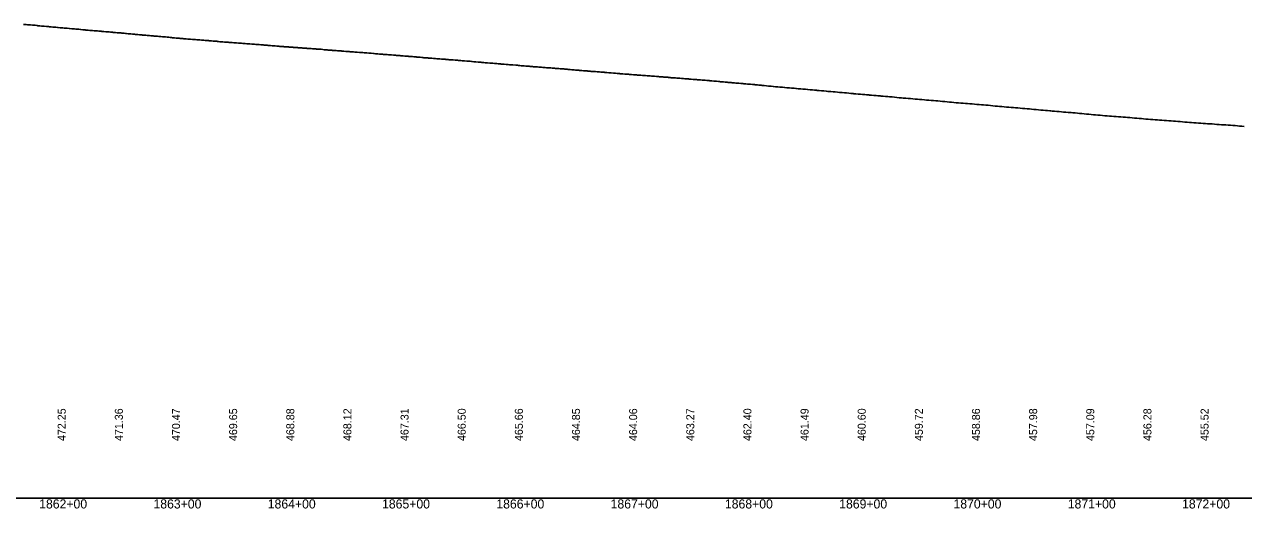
# Model space of a CAD drawing. Extents: x 2017200 to 2047700, y 854850 to 893350.
# Drawn here: x 2041163 to 2042230, y 856091 to 856515 of the extents above; entities that cross this region are included whole.
import ezdxf

# ---------------------------------------------------------------- set-up
doc = ezdxf.new("R2010")
doc.units = 0
for name, color, linetype in [('RD_DDB_Profile_EX', 7, 'Continuous'), ('RD_DDB_StaTX', 7, 'Continuous'), ('RD_DDB_StripGrade', 7, 'Continuous'), ('RD_GPK_Profile_Cell', 7, 'Continuous')]:
    doc.layers.add(name, color=color, linetype=linetype)

msp = doc.modelspace()

# ---------------------------------------------------------------- linework, layer by layer
at = {"layer": 'RD_DDB_Profile_EX'}
msp.add_lwpolyline([(2041162.2, 856514.6), (2041163.9, 856514.5), (2041164.3, 856514.5), (2041165.5, 856514.3), (2041166.3, 856514.3), (2041167.8, 856514.2), (2041168.2, 856514.1), (2041169.9, 856514), (2041170.2, 856513.9), (2041172.2, 856513.8), (2041174, 856513.6), (2041174.5, 856513.5), (2041175.6, 856513.4), (2041176.3, 856513.4), (2041177.8, 856513.2), (2041178.3, 856513.2), (2041179.9, 856513.1), (2041180.2, 856513), (2041182.2, 856512.8), (2041184.2, 856512.7), (2041184.6, 856512.6), (2041185.6, 856512.5), (2041186.4, 856512.5), (2041187.8, 856512.3), (2041188.3, 856512.3), (2041189.9, 856512.1), (2041190.3, 856512.1), (2041191.9, 856511.9), (2041192.3, 856511.9), (2041194.2, 856511.7), (2041194.8, 856511.7), (2041195.6, 856511.6), (2041196.5, 856511.5), (2041197.8, 856511.4), (2041198.4, 856511.4), (2041199.9, 856511.2), (2041200.3, 856511.2), (2041202, 856511.1), (2041202.3, 856511), (2041204.3, 856510.8), (2041206, 856510.7), (2041206.6, 856510.6), (2041207.9, 856510.5), (2041208.5, 856510.5), (2041209.9, 856510.4), (2041210.4, 856510.3), (2041212, 856510.1), (2041212.3, 856510.1), (2041214, 856510), (2041214.3, 856509.9), (2041216, 856509.8), (2041216.7, 856509.7), (2041217.9, 856509.6), (2041218.6, 856509.6), (2041220, 856509.4), (2041220.5, 856509.4), (2041222, 856509.3), (2041222.4, 856509.2), (2041224, 856509.1), (2041224.3, 856509), (2041226, 856508.9), (2041226.9, 856508.9), (2041228, 856508.7), (2041228.6, 856508.7), (2041230, 856508.6), (2041230.5, 856508.5), (2041232, 856508.4), (2041232.4, 856508.3), (2041234.1, 856508.2), (2041234.4, 856508.2), (2041236.1, 856508), (2041237.1, 856508), (2041238.1, 856507.9), (2041238.8, 856507.8), (2041240.1, 856507.7), (2041240.6, 856507.6), (2041242.1, 856507.5), (2041242.5, 856507.4), (2041244.1, 856507.3), (2041244.5, 856507.3), (2041246.1, 856507.1), (2041247.3, 856507.1), (2041248.2, 856507), (2041249, 856506.9), (2041250.2, 856506.8), (2041251.4, 856506.7), (2041252.1, 856506.6), (2041253.6, 856506.5), (2041254.1, 856506.4), (2041255.7, 856506.3), (2041256.1, 856506.3), (2041257.5, 856506.2), (2041258.3, 856506.1), (2041259.1, 856506), (2041260.2, 856505.9), (2041261.4, 856505.8), (2041262.2, 856505.7), (2041263.6, 856505.6), (2041264.2, 856505.5), (2041265.7, 856505.4), (2041266.2, 856505.3), (2041267.8, 856505.2), (2041268.4, 856505.2), (2041269.1, 856505.1), (2041270.3, 856505), (2041271.5, 856504.9), (2041272.3, 856504.8), (2041273.6, 856504.7), (2041274.2, 856504.6), (2041275.7, 856504.5), (2041276.2, 856504.4), (2041277.8, 856504.3), (2041278.6, 856504.2), (2041279.2, 856504.2), (2041280.4, 856504.1), (2041281.5, 856504), (2041282.3, 856503.9), (2041283.7, 856503.8), (2041284.3, 856503.7), (2041285.8, 856503.6), (2041286.3, 856503.6), (2041287.8, 856503.4), (2041288.8, 856503.3), (2041289.2, 856503.3), (2041290.5, 856503.2), (2041291.6, 856503.1), (2041292.4, 856503), (2041293.7, 856502.9), (2041294.3, 856502.8), (2041295.8, 856502.7), (2041296.3, 856502.7), (2041297.9, 856502.5), (2041298.3, 856502.5), (2041299.3, 856502.4), (2041300.7, 856502.3), (2041301.6, 856502.2), (2041302.5, 856502.1), (2041303.8, 856502), (2041304.4, 856501.9), (2041305.9, 856501.8), (2041306.4, 856501.8), (2041307.9, 856501.7), (2041308.3, 856501.7), (2041309.9, 856501.5), (2041310.8, 856501.5), (2041311.7, 856501.4), (2041312.6, 856501.3), (2041313.8, 856501.2), (2041314.5, 856501.1), (2041315.9, 856501), (2041316.4, 856501), (2041317.9, 856500.9), (2041318.4, 856500.8), (2041320, 856500.7), (2041321, 856500.6), (2041321.8, 856500.6), (2041322.7, 856500.5), (2041323.9, 856500.4), (2041324.5, 856500.3), (2041326, 856500.1), (2041326.5, 856500.1), (2041328, 856500), (2041328.4, 856500), (2041330, 856499.9), (2041331.1, 856499.8), (2041331.9, 856499.7), (2041332.8, 856499.6), (2041334, 856499.5), (2041334.6, 856499.4), (2041336, 856499.3), (2041336.5, 856499.3), (2041338, 856499.2), (2041338.4, 856499.2), (2041340, 856499.1), (2041341.3, 856499), (2041342, 856498.9), (2041342.9, 856498.8), (2041344.1, 856498.8), (2041344.7, 856498.7), (2041346.1, 856498.6), (2041346.6, 856498.5), (2041348.1, 856498.4), (2041348.5, 856498.4), (2041350.1, 856498.2), (2041351.6, 856498.2), (2041352.1, 856498.1), (2041352.7, 856498.1), (2041354.1, 856498), (2041355.3, 856497.9), (2041356.1, 856497.8), (2041357.5, 856497.7), (2041358.1, 856497.6), (2041359.6, 856497.5), (2041360.1, 856497.5), (2041361.9, 856497.4), (2041362.3, 856497.3), (2041362.7, 856497.3), (2041364.2, 856497.2), (2041365.3, 856497.1), (2041366.2, 856497), (2041367.5, 856496.9), (2041368.2, 856496.9), (2041369.6, 856496.8), (2041370.2, 856496.7), (2041371.7, 856496.6), (2041372.8, 856496.5), (2041374.3, 856496.4), (2041375.3, 856496.3), (2041376.3, 856496.2), (2041377.6, 856496.1), (2041378.2, 856496.1), (2041379.7, 856495.9), (2041380.2, 856495.9), (2041381.8, 856495.8), (2041382.2, 856495.8), (2041383.8, 856495.6), (2041384.4, 856495.6), (2041385.4, 856495.5), (2041386.3, 856495.4), (2041387.6, 856495.4), (2041388.3, 856495.3), (2041389.7, 856495.2), (2041390.3, 856495.1), (2041391.8, 856495), (2041392.2, 856495), (2041393.9, 856494.9), (2041394.6, 856494.8), (2041395.5, 856494.8), (2041396.4, 856494.7), (2041397.7, 856494.6), (2041398.4, 856494.5), (2041399.8, 856494.4), (2041400.3, 856494.4), (2041401.8, 856494.3), (2041402.3, 856494.2), (2041403.9, 856494.1), (2041404.7, 856494), (2041405.5, 856494), (2041406.5, 856493.9), (2041407.7, 856493.8), (2041408.4, 856493.8), (2041409.8, 856493.7), (2041410.4, 856493.6), (2041411.9, 856493.5), (2041412.3, 856493.5), (2041413.9, 856493.4), (2041414.9, 856493.3), (2041415.6, 856493.2), (2041416.6, 856493.2), (2041417.8, 856493.1), (2041418.5, 856493), (2041419.9, 856492.9), (2041420.4, 856492.9), (2041421.9, 856492.8), (2041422.4, 856492.8), (2041423.9, 856492.6), (2041425.1, 856492.5), (2041425.7, 856492.5), (2041426.8, 856492.4), (2041427.8, 856492.3), (2041428.6, 856492.2), (2041429.9, 856492.1), (2041430.5, 856492.1), (2041432, 856492), (2041432.4, 856491.9), (2041434, 856491.8), (2041435.4, 856491.7), (2041435.8, 856491.7), (2041436.9, 856491.6), (2041437.9, 856491.5), (2041438.7, 856491.5), (2041440, 856491.4), (2041440.6, 856491.3), (2041442, 856491.2), (2041442.5, 856491.2), (2041444, 856491), (2041445.9, 856490.9), (2041447.1, 856490.8), (2041448, 856490.7), (2041448.8, 856490.7), (2041450, 856490.6), (2041450.7, 856490.6), (2041452.1, 856490.4), (2041452.6, 856490.4), (2041454.1, 856490.3), (2041456.2, 856490.1), (2041458.1, 856490), (2041458.9, 856489.9), (2041460.1, 856489.8), (2041460.7, 856489.8), (2041462.1, 856489.7), (2041462.6, 856489.6), (2041464.1, 856489.5), (2041466.4, 856489.3), (2041468.2, 856489.2), (2041469, 856489.1), (2041470.2, 856489), (2041471.4, 856488.9), (2041472.2, 856488.8), (2041473.5, 856488.7), (2041474.2, 856488.6), (2041475.6, 856488.5), (2041476.5, 856488.5), (2041476.9, 856488.4), (2041478.4, 856488.3), (2041479.1, 856488.3), (2041480.3, 856488.2), (2041481.4, 856488.1), (2041482.2, 856488), (2041483.6, 856487.9), (2041484.2, 856487.9), (2041485.7, 856487.7), (2041486.2, 856487.7), (2041487.7, 856487.6), (2041488.5, 856487.5), (2041489.1, 856487.5), (2041490.4, 856487.3), (2041491.4, 856487.3), (2041492.3, 856487.2), (2041493.6, 856487.1), (2041494.3, 856487), (2041495.7, 856486.9), (2041496.2, 856486.8), (2041497.8, 856486.7), (2041498.7, 856486.7), (2041499.2, 856486.6), (2041500.5, 856486.5), (2041501.5, 856486.4), (2041502.4, 856486.4), (2041503.6, 856486.3), (2041504.3, 856486.2), (2041505.7, 856486.1), (2041506.3, 856486), (2041507.8, 856485.9), (2041508.9, 856485.9), (2041509.3, 856485.8), (2041510.6, 856485.7), (2041511.6, 856485.6), (2041512.5, 856485.5), (2041513.7, 856485.5), (2041514.4, 856485.4), (2041515.8, 856485.3), (2041516.4, 856485.2), (2041517.8, 856485.1), (2041519.4, 856485), (2041520.8, 856484.9), (2041521.6, 856484.8), (2041522.6, 856484.7), (2041523.8, 856484.6), (2041524.5, 856484.5), (2041525.8, 856484.4), (2041526.4, 856484.4), (2041527.9, 856484.3), (2041529.5, 856484.2), (2041530.9, 856484.1), (2041531.7, 856484), (2041532.7, 856483.9), (2041533.8, 856483.8), (2041534.6, 856483.7), (2041535.9, 856483.6), (2041536.5, 856483.6), (2041537.9, 856483.5), (2041539.7, 856483.3), (2041541.1, 856483.2), (2041541.8, 856483.2), (2041542.8, 856483.1), (2041543.9, 856483), (2041544.6, 856482.9), (2041546, 856482.8), (2041546.5, 856482.7), (2041548, 856482.6), (2041550.1, 856482.5), (2041551.2, 856482.4), (2041551.9, 856482.3), (2041552.9, 856482.3), (2041554, 856482.2), (2041554.7, 856482.1), (2041556, 856481.9), (2041556.6, 856481.9), (2041558, 856481.8), (2041560, 856481.6), (2041560.6, 856481.6), (2041561.5, 856481.5), (2041562.1, 856481.5), (2041563.1, 856481.4), (2041564.1, 856481.3), (2041564.9, 856481.2), (2041566.1, 856481.1), (2041566.7, 856481), (2041568.1, 856480.9), (2041570.2, 856480.8), (2041571.1, 856480.7), (2041572.2, 856480.6), (2041572.7, 856480.6), (2041574.2, 856480.5), (2041575.1, 856480.4), (2041576.2, 856480.3), (2041577.3, 856480.2), (2041578.1, 856480.1), (2041579.5, 856480), (2041580.1, 856479.9), (2041582, 856479.8), (2041582.4, 856479.8), (2041582.8, 856479.8), (2041584.3, 856479.6), (2041585.2, 856479.6), (2041586.2, 856479.4), (2041587.4, 856479.3), (2041588.2, 856479.3), (2041589.5, 856479.2), (2041590.2, 856479.1), (2041592.9, 856478.9), (2041594.4, 856478.8), (2041595.3, 856478.7), (2041596.3, 856478.6), (2041597.5, 856478.5), (2041598.3, 856478.4), (2041599.6, 856478.3), (2041600.3, 856478.3), (2041601.7, 856478.2), (2041602.9, 856478.1), (2041604.5, 856478), (2041605.3, 856477.9), (2041606.4, 856477.8), (2041607.5, 856477.7), (2041608.4, 856477.6), (2041609.7, 856477.5), (2041610.3, 856477.5), (2041611.7, 856477.4), (2041613, 856477.3), (2041614.7, 856477.2), (2041615.4, 856477.1), (2041616.5, 856477), (2041617.6, 856477), (2041618.4, 856476.8), (2041619.7, 856476.7), (2041620.4, 856476.7), (2041621.8, 856476.6), (2041622.3, 856476.5), (2041623.4, 856476.5), (2041624.8, 856476.4), (2041625.5, 856476.3), (2041626.6, 856476.2), (2041627.7, 856476.1), (2041628.5, 856476), (2041629.8, 856475.9), (2041630.4, 856475.9), (2041631.8, 856475.8), (2041632.4, 856475.7), (2041633.4, 856475.7), (2041633.9, 856475.6), (2041635, 856475.6), (2041635.6, 856475.5), (2041636.7, 856475.4), (2041637.8, 856475.3), (2041638.6, 856475.2), (2041639.9, 856475.1), (2041640.5, 856475.1), (2041641.9, 856474.9), (2041642.4, 856474.9), (2041643.9, 856474.8), (2041645.2, 856474.7), (2041645.8, 856474.7), (2041646.8, 856474.6), (2041647.9, 856474.5), (2041648.7, 856474.4), (2041649.9, 856474.3), (2041650.6, 856474.2), (2041652, 856474.1), (2041652.5, 856474.1), (2041654, 856474), (2041655.4, 856473.9), (2041655.9, 856473.8), (2041657, 856473.8), (2041658, 856473.7), (2041658.7, 856473.5), (2041660, 856473.4), (2041660.6, 856473.4), (2041662, 856473.3), (2041662.5, 856473.3), (2041664, 856473.1), (2041665.6, 856473), (2041666, 856473), (2041667.1, 856472.9), (2041668.1, 856472.8), (2041668.8, 856472.8), (2041670.1, 856472.7), (2041670.7, 856472.6), (2041672.1, 856472.5), (2041672.6, 856472.4), (2041674.1, 856472.3), (2041676.4, 856472.2), (2041678.2, 856472), (2041679.1, 856472), (2041680.1, 856471.9), (2041681.4, 856471.7), (2041682.1, 856471.7), (2041683.5, 856471.6), (2041684.1, 856471.5), (2041686.5, 856471.3), (2041688.3, 856471.2), (2041689.1, 856471.1), (2041690.2, 856471), (2041691.4, 856471), (2041692.2, 856470.9), (2041693.6, 856470.7), (2041694.2, 856470.7), (2041695.7, 856470.6), (2041696.7, 856470.5), (2041698.4, 856470.4), (2041699.2, 856470.3), (2041700.3, 856470.3), (2041701.5, 856470.2), (2041702.3, 856470.1), (2041703.6, 856470), (2041704.2, 856469.9), (2041705.7, 856469.8), (2041706.2, 856469.8), (2041707.8, 856469.7), (2041708.5, 856469.6), (2041709.3, 856469.5), (2041710.4, 856469.5), (2041711.5, 856469.4), (2041712.3, 856469.3), (2041713.7, 856469.2), (2041714.3, 856469.2), (2041715.8, 856469.1), (2041716.3, 856469), (2041717.8, 856468.9), (2041718.7, 856468.8), (2041719.3, 856468.8), (2041720.5, 856468.7), (2041721.6, 856468.6), (2041722.4, 856468.5), (2041723.7, 856468.4), (2041724.3, 856468.4), (2041725.8, 856468.3), (2041726.3, 856468.2), (2041727.9, 856468.1), (2041728.9, 856468), (2041729.5, 856468), (2041730.6, 856467.9), (2041731.7, 856467.8), (2041732.5, 856467.8), (2041733.8, 856467.7), (2041734.4, 856467.6), (2041735.9, 856467.5), (2041736.4, 856467.5), (2041737.9, 856467.3), (2041739.1, 856467.3), (2041739.5, 856467.2), (2041740.7, 856467.1), (2041741.8, 856467), (2041742.6, 856467), (2041743.9, 856466.9), (2041744.5, 856466.8), (2041745.9, 856466.7), (2041746.4, 856466.7), (2041748, 856466.5), (2041748.3, 856466.5), (2041749.3, 856466.4), (2041749.7, 856466.4), (2041750.8, 856466.3), (2041751.9, 856466.2), (2041752.6, 856466.2), (2041753.9, 856466), (2041754.5, 856466), (2041756, 856465.9), (2041756.4, 856465.8), (2041758, 856465.7), (2041758.4, 856465.7), (2041760, 856465.5), (2041760.9, 856465.5), (2041761.9, 856465.4), (2041762.7, 856465.3), (2041764, 856465.2), (2041764.5, 856465.1), (2041766, 856465), (2041766.5, 856465), (2041768.1, 856464.8), (2041768.4, 856464.8), (2041770.1, 856464.7), (2041771.1, 856464.6), (2041772, 856464.5), (2041772.8, 856464.4), (2041774.1, 856464.3), (2041774.6, 856464.3), (2041776.1, 856464.1), (2041776.5, 856464.1), (2041778.1, 856464), (2041778.4, 856463.9), (2041780.1, 856463.8), (2041781.2, 856463.7), (2041782.1, 856463.6), (2041783, 856463.5), (2041784.1, 856463.5), (2041785.4, 856463.3), (2041786.1, 856463.3), (2041787.6, 856463.1), (2041788.1, 856463.1), (2041789.7, 856462.9), (2041790.1, 856462.9), (2041791.4, 856462.8), (2041792.3, 856462.7), (2041793.1, 856462.6), (2041794.2, 856462.5), (2041795.5, 856462.4), (2041796.2, 856462.4), (2041797.6, 856462.2), (2041798.2, 856462.2), (2041799.8, 856462), (2041800.2, 856462), (2041801.7, 856461.9), (2041802.4, 856461.8), (2041803.1, 856461.7), (2041804.3, 856461.6), (2041805.6, 856461.5), (2041806.2, 856461.4), (2041807.7, 856461.3), (2041808.2, 856461.2), (2041809.8, 856461.1), (2041810.2, 856461.1), (2041812.2, 856460.9), (2041814, 856460.7), (2041814.3, 856460.7), (2041815.7, 856460.6), (2041816.3, 856460.5), (2041817.9, 856460.4), (2041818.2, 856460.3), (2041820.2, 856460.1), (2041822.2, 856460), (2041824, 856459.8), (2041824.4, 856459.8), (2041825.7, 856459.7), (2041826.3, 856459.6), (2041827.9, 856459.5), (2041828.3, 856459.4), (2041829.9, 856459.2), (2041830.3, 856459.2), (2041832.2, 856459.1), (2041834, 856458.9), (2041834.5, 856458.9), (2041835.7, 856458.8), (2041836.4, 856458.7), (2041837.9, 856458.6), (2041838.3, 856458.5), (2041839.9, 856458.3), (2041840.3, 856458.3), (2041842.3, 856458.1), (2041844, 856458), (2041844.6, 856458), (2041845.8, 856457.9), (2041846.4, 856457.8), (2041848, 856457.7), (2041848.3, 856457.7), (2041850.3, 856457.4), (2041852.3, 856457.3), (2041854.3, 856457.1), (2041854.7, 856457.1), (2041855.9, 856457), (2041856.5, 856456.9), (2041858, 856456.8), (2041858.4, 856456.7), (2041860.3, 856456.5), (2041862.3, 856456.4), (2041864.3, 856456.2), (2041864.8, 856456.1), (2041866, 856456), (2041866.5, 856456), (2041868, 856455.8), (2041868.4, 856455.8), (2041870.4, 856455.6), (2041872.3, 856455.5), (2041874.3, 856455.3), (2041876.1, 856455.1), (2041876.6, 856455.1), (2041878.1, 856455), (2041878.4, 856454.9), (2041880.4, 856454.7), (2041882.3, 856454.6), (2041884.3, 856454.4), (2041886.1, 856454.2), (2041886.6, 856454.2), (2041888.1, 856454.1), (2041888.5, 856454), (2041890.4, 856453.9), (2041892.3, 856453.7), (2041894.3, 856453.5), (2041896.1, 856453.4), (2041896.8, 856453.3), (2041898.2, 856453.2), (2041899.6, 856453.1), (2041900.2, 856453), (2041901.8, 856452.9), (2041902.2, 856452.8), (2041904.2, 856452.7), (2041906.2, 856452.5), (2041906.8, 856452.4), (2041908.2, 856452.3), (2041909.7, 856452.2), (2041910.2, 856452.1), (2041911.9, 856452), (2041912.2, 856451.9), (2041914.2, 856451.8), (2041916.2, 856451.6), (2041918.3, 856451.4), (2041919.7, 856451.3), (2041920.3, 856451.2), (2041921.9, 856451.1), (2041922.2, 856451.1), (2041924.2, 856450.9), (2041926.2, 856450.7), (2041928.4, 856450.5), (2041929.8, 856450.4), (2041930.3, 856450.4), (2041931.9, 856450.2), (2041932.2, 856450.2), (2041934.2, 856450), (2041936.2, 856449.9), (2041938.2, 856449.7), (2041940.3, 856449.5), (2041942.3, 856449.3), (2041944.2, 856449.1), (2041946.2, 856448.9), (2041948.2, 856448.8), (2041950.3, 856448.6), (2041952.2, 856448.4), (2041954.2, 856448.2), (2041956.2, 856448.1), (2041958.2, 856447.9), (2041960.3, 856447.7), (2041962.2, 856447.6), (2041964.2, 856447.4), (2041966.2, 856447.2), (2041968.2, 856447), (2041970.2, 856446.9), (2041972.2, 856446.7), (2041974.2, 856446.5), (2041976.2, 856446.3), (2041978.2, 856446.1), (2041980.2, 856446), (2041982.2, 856445.8), (2041982.8, 856445.7), (2041984.2, 856445.6), (2041986.2, 856445.5), (2041988.2, 856445.3), (2041990.2, 856445.1), (2041992.2, 856445), (2041994.2, 856444.8), (2041996.2, 856444.6), (2041998.2, 856444.5), (2042000.2, 856444.3), (2042002.2, 856444.1), (2042004.2, 856443.9), (2042006.2, 856443.8), (2042008.2, 856443.6), (2042010.2, 856443.4), (2042012.2, 856443.2), (2042014.2, 856443.1), (2042016.2, 856442.9), (2042018.2, 856442.7), (2042020.2, 856442.5), (2042022.2, 856442.3), (2042024.2, 856442.2), (2042026.2, 856442), (2042028.2, 856441.8), (2042030.2, 856441.6), (2042032.2, 856441.5), (2042034.2, 856441.3), (2042036.2, 856441.1), (2042038.2, 856440.9), (2042040.2, 856440.7), (2042042.2, 856440.6), (2042044.2, 856440.4), (2042046.2, 856440.2), (2042048.2, 856440), (2042050.2, 856439.9), (2042052.2, 856439.7), (2042054.2, 856439.5), (2042056.2, 856439.3), (2042057.5, 856439.2), (2042058.2, 856439.2), (2042060.2, 856439), (2042061, 856438.9), (2042062.2, 856438.8), (2042064.2, 856438.7), (2042066.2, 856438.5), (2042068.2, 856438.3), (2042070.2, 856438.1), (2042072.2, 856437.9), (2042074.2, 856437.8), (2042076.2, 856437.6), (2042078.2, 856437.5), (2042078.7, 856437.4), (2042080.2, 856437.3), (2042082.2, 856437.1), (2042084.2, 856436.9), (2042086.2, 856436.7), (2042088.2, 856436.5), (2042090.2, 856436.4), (2042092.2, 856436.2), (2042094.2, 856436), (2042096.2, 856435.8), (2042098.2, 856435.6), (2042100.2, 856435.4), (2042102.2, 856435.2), (2042104.2, 856435.1), (2042106.2, 856434.9), (2042108.2, 856434.7), (2042110.2, 856434.5), (2042112.2, 856434.3), (2042114.2, 856434.2), (2042116.2, 856434), (2042118.2, 856433.9), (2042120.2, 856433.7), (2042122.2, 856433.6), (2042124.2, 856433.4), (2042126.2, 856433.3), (2042128.2, 856433.1), (2042130.2, 856433), (2042132.2, 856432.8), (2042134.2, 856432.6), (2042136.2, 856432.5), (2042138.2, 856432.3), (2042140.2, 856432.2), (2042142.2, 856432), (2042144.2, 856431.8), (2042146.2, 856431.7), (2042148.2, 856431.5), (2042150.2, 856431.4), (2042152.2, 856431.2), (2042154.2, 856431.1), (2042156.2, 856430.9), (2042158.2, 856430.7), (2042160.2, 856430.6), (2042162.2, 856430.5), (2042164.2, 856430.3), (2042166.2, 856430.2), (2042168.2, 856430), (2042170.2, 856429.8), (2042172.2, 856429.7), (2042174.2, 856429.5), (2042176.2, 856429.4), (2042178.2, 856429.2), (2042180.3, 856429.1), (2042182.2, 856428.9), (2042184.2, 856428.8), (2042186.2, 856428.6), (2042188.2, 856428.5), (2042190.3, 856428.3), (2042192.2, 856428.2), (2042194.2, 856428), (2042196.2, 856427.9), (2042198.2, 856427.7), (2042200.2, 856427.6), (2042202.2, 856427.5), (2042204.2, 856427.3), (2042206.2, 856427.1), (2042208.2, 856427), (2042210.2, 856426.8), (2042212.2, 856426.7), (2042214.2, 856426.6), (2042216.2, 856426.4), (2042218.2, 856426.3), (2042220.2, 856426.1), (2042222.3, 856426), (2042224.2, 856425.8), (2042226.2, 856425.7), (2042228.2, 856425.5), (2042230.2, 856425.3)], dxfattribs=at)
at = {"layer": 'RD_GPK_Profile_Cell'}
msp.add_line((2020500, 856100), (2047700, 856100), dxfattribs=at)

# ---------------------------------------------------------------- texts
at = {"layer": 'RD_DDB_StaTX'}
for s, p in [('1862+00', (2041175.8, 856091)), ('1863+00', (2041275.8, 856091)), ('1864+00', (2041375.8, 856091)), ('1865+00', (2041475.8, 856091)), ('1866+00', (2041575.8, 856091)), ('1867+00', (2041675.8, 856091)), ('1868+00', (2041775.8, 856091)), ('1869+00', (2041875.8, 856091)), ('1870+00', (2041975.8, 856091)), ('1871+00', (2042075.8, 856091)), ('1872+00', (2042175.8, 856091))]:
    msp.add_text(s, height=8, dxfattribs=at).set_placement(p)
at = {"layer": 'RD_DDB_StripGrade'}
for s, p in [('472.25', (2041199, 856150)), ('471.36', (2041249, 856150)), ('470.47', (2041299, 856150)), ('469.65', (2041349, 856150)), ('468.88', (2041399, 856150)), ('468.12', (2041449, 856150)), ('467.31', (2041499, 856150)), ('466.50', (2041549, 856150)), ('465.66', (2041599, 856150)), ('464.85', (2041649, 856150)), ('464.06', (2041699, 856150)), ('463.27', (2041749, 856150)), ('462.40', (2041799, 856150)), ('461.49', (2041849, 856150)), ('460.60', (2041899, 856150)), ('459.72', (2041949, 856150)), ('458.86', (2041999, 856150)), ('457.98', (2042049, 856150)), ('457.09', (2042099, 856150)), ('456.28', (2042149, 856150)), ('455.52', (2042199, 856150))]:
    msp.add_text(s, height=7, rotation=90, dxfattribs=at).set_placement(p)

doc.saveas('drawing.dxf')
